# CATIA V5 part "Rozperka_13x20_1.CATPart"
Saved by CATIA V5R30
Part number: Rozperka_13x20_1
Definition: ISO 13337-13x20_2
Nomenclature: ISO 13337-13x20_2
Source: Unknown
Description: PART--DESC
Bounding box of the stored display mesh (mm): x -136 to -123.025, y 12.006 to 24.994, z 29.7 to 49.7
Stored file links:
  E:\Bakalarka\Model\Forma_v7\Rozperka_13x20_1.CATPart
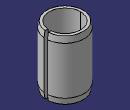
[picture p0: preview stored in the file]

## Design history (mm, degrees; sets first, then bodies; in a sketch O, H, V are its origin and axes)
Body1 "MANIFOLD_SOLID_BREP #3682" (main body)
  Solid1: solid without history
